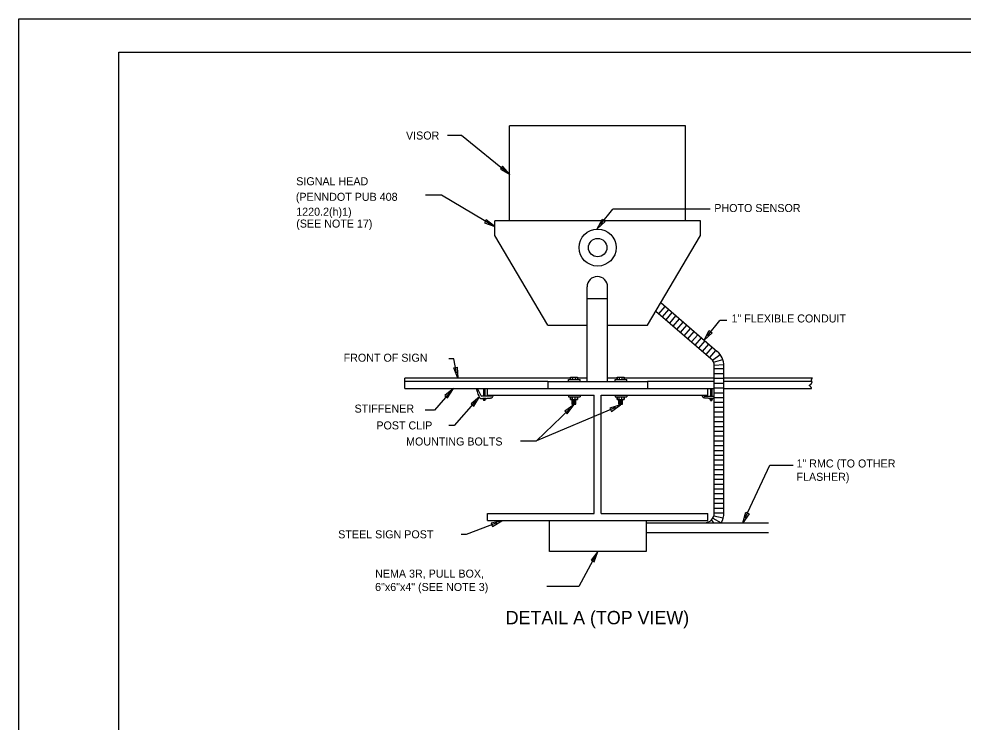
# Model space of a CAD drawing. Extents: x 1299104.6 to 1299141.5, y 239713.3 to 239735.3.
# Drawn here: x 1299104.62 to 1299118.77, y 239724.74 to 239735.27 of the extents above; entities that cross this region are included whole.
import ezdxf

# ---------------------------------------------------------------- set-up
doc = ezdxf.new("R2010")
doc.units = 0
for name, color, linetype in [('DIM TXT', 7, 'Continuous'), ('GS_plotshape_p', 7, 'Continuous'), ('Level 1', 7, 'Continuous'), ('PTEXT', 7, 'Continuous')]:
    doc.layers.add(name, color=color, linetype=linetype)

msp = doc.modelspace()

# ---------------------------------------------------------------- linework, layer by layer
at = {"layer": 'DIM TXT'}
for p, q in [((1299111.047, 239733.529), (1299111.254, 239733.529)), ((1299111.254, 239733.529), (1299111.982, 239732.944)), ((1299110.714, 239732.638), (1299110.957, 239732.638)), ((1299110.957, 239732.638), (1299111.755, 239732.162)), ((1299113.338, 239732.192), (1299113.522, 239732.422)), ((1299114.98, 239732.423), (1299113.522, 239732.422)), ((1299114.941, 239730.526), (1299115.125, 239730.756)), ((1299115.23, 239730.756), (1299115.125, 239730.756)), ((1299111.139, 239730.179), (1299111.065, 239730.179)), ((1299111.183, 239729.972), (1299111.139, 239730.179)), ((1299111.081, 239729.677), (1299110.849, 239729.413)), ((1299111.472, 239729.551), (1299111.148, 239729.182)), ((1299110.849, 239729.413), (1299110.712, 239729.413)), ((1299113.565, 239729.453), (1299112.38, 239728.951)), ((1299112.881, 239729.433), (1299112.38, 239728.951)), ((1299111.148, 239729.182), (1299111.065, 239729.182)), ((1299112.141, 239728.951), (1299112.38, 239728.951)), ((1299115.507, 239727.799), (1299115.877, 239728.587)), ((1299115.877, 239728.587), (1299116.225, 239728.587)), ((1299111.784, 239727.724), (1299111.326, 239727.549)), ((1299111.326, 239727.549), (1299111.252, 239727.549)), ((1299113.261, 239727.226), (1299113.014, 239726.77)), ((1299113.014, 239726.77), (1299112.534, 239726.77))]:
    msp.add_line(p, q, dxfattribs=at)
for points in [[(1299111.872, 239733.066), (1299111.838, 239733.024), (1299111.982, 239732.944)], [(1299111.627, 239732.264), (1299111.6, 239732.217), (1299111.755, 239732.162)], [(1299113.367, 239732.272), (1299113.409, 239732.239), (1299113.289, 239732.128)], [(1299114.969, 239730.606), (1299115.012, 239730.573), (1299114.891, 239730.462)], [(1299111.139, 239730.046), (1299111.192, 239730.057), (1299111.2, 239729.893)], [(1299111.007, 239729.634), (1299111.047, 239729.598), (1299111.135, 239729.737)], [(1299111.398, 239729.509), (1299111.438, 239729.473), (1299111.526, 239729.611)], [(1299112.804, 239729.397), (1299112.841, 239729.358), (1299112.939, 239729.49)], [(1299113.48, 239729.441), (1299113.505, 239729.393), (1299113.637, 239729.49)], [(1299115.517, 239727.884), (1299115.566, 239727.861), (1299115.473, 239727.726)], [(1299111.698, 239727.72), (1299111.718, 239727.67), (1299111.859, 239727.753)], [(1299113.199, 239727.167), (1299113.246, 239727.141), (1299113.3, 239727.297)]]:
    msp.add_lwpolyline(points, close=True, dxfattribs=at)
at = {"layer": 'GS_plotshape_p'}
msp.add_lwpolyline([(1299104.622, 239735.273), (1299138.622, 239735.273), (1299138.622, 239713.273), (1299104.622, 239713.273)], close=True, dxfattribs=at)
at = {"layer": 'Level 1'}
msp.add_lwpolyline([(1299138.122, 239713.773), (1299106.122, 239713.773), (1299106.122, 239734.773), (1299138.122, 239734.773)], close=True, dxfattribs=at)
at = {"layer": 'PTEXT'}
for p, q in [((1299114.614, 239733.673), (1299111.977, 239733.673)), ((1299111.977, 239732.249), (1299111.977, 239733.673)), ((1299114.614, 239732.249), (1299114.614, 239733.673)), ((1299114.836, 239732.249), (1299111.756, 239732.249)), ((1299111.756, 239732.027), (1299111.756, 239732.249)), ((1299114.836, 239732.027), (1299114.836, 239732.249)), ((1299112.551, 239730.686), (1299111.756, 239732.027)), ((1299114.041, 239730.686), (1299114.836, 239732.027)), ((1299113.138, 239729.84), (1299113.138, 239731.26)), ((1299113.446, 239729.84), (1299113.446, 239731.26)), ((1299113.138, 239731.086), (1299113.446, 239731.086)), ((1299114.212, 239730.857), (1299114.306, 239730.967)), ((1299114.241, 239731.023), (1299115.088, 239730.293)), ((1299114.166, 239730.897), (1299114.994, 239730.184)), ((1299114.267, 239730.81), (1299114.361, 239730.92)), ((1299114.321, 239730.763), (1299114.415, 239730.873)), ((1299114.376, 239730.716), (1299114.47, 239730.825)), ((1299112.551, 239730.686), (1299113.138, 239730.686)), ((1299113.446, 239730.686), (1299114.041, 239730.686)), ((1299114.43, 239730.669), (1299114.524, 239730.778)), ((1299114.485, 239730.622), (1299114.579, 239730.731)), ((1299114.539, 239730.575), (1299114.633, 239730.684)), ((1299114.594, 239730.528), (1299114.688, 239730.637)), ((1299114.648, 239730.481), (1299114.742, 239730.59)), ((1299114.703, 239730.434), (1299114.797, 239730.543)), ((1299114.757, 239730.387), (1299114.851, 239730.496)), ((1299114.812, 239730.34), (1299114.906, 239730.449)), ((1299114.866, 239730.293), (1299114.96, 239730.402)), ((1299114.921, 239730.246), (1299115.015, 239730.355)), ((1299114.975, 239730.199), (1299115.069, 239730.308)), ((1299115.016, 239730.159), (1299115.132, 239730.245)), ((1299115.033, 239730.129), (1299115.171, 239730.169)), ((1299115.043, 239730.088), (1299115.187, 239730.095)), ((1299115.044, 239727.87), (1299115.044, 239730.074)), ((1299115.044, 239730.034), (1299115.188, 239730.034)), ((1299115.044, 239729.962), (1299115.188, 239729.962)), ((1299115.188, 239727.87), (1299115.188, 239730.074)), ((1299110.407, 239729.737), (1299110.407, 239729.892)), ((1299112.889, 239729.892), (1299110.407, 239729.892)), ((1299112.551, 239729.84), (1299110.407, 239729.84)), ((1299112.551, 239729.84), (1299114.041, 239729.84)), ((1299112.551, 239729.84), (1299112.551, 239729.737)), ((1299112.859, 239729.87), (1299113.033, 239729.87)), ((1299112.859, 239729.845), (1299112.859, 239729.87)), ((1299112.889, 239729.906), (1299112.995, 239729.906)), ((1299112.889, 239729.906), (1299112.889, 239729.87)), ((1299112.889, 239729.88), (1299112.889, 239729.906)), ((1299112.919, 239729.906), (1299112.919, 239729.87)), ((1299112.96, 239729.906), (1299112.96, 239729.87)), ((1299112.995, 239729.87), (1299112.995, 239729.906)), ((1299112.995, 239729.906), (1299112.995, 239729.88)), ((1299113.138, 239729.892), (1299112.995, 239729.892)), ((1299113.033, 239729.845), (1299113.033, 239729.87)), ((1299113.588, 239729.892), (1299113.446, 239729.892)), ((1299113.559, 239729.87), (1299113.733, 239729.87)), ((1299113.559, 239729.845), (1299113.559, 239729.87)), ((1299113.588, 239729.906), (1299113.588, 239729.87)), ((1299113.588, 239729.88), (1299113.588, 239729.906)), ((1299113.588, 239729.906), (1299113.694, 239729.906)), ((1299113.618, 239729.906), (1299113.618, 239729.87)), ((1299113.659, 239729.906), (1299113.659, 239729.87)), ((1299113.694, 239729.87), (1299113.694, 239729.906)), ((1299113.694, 239729.906), (1299113.694, 239729.88)), ((1299115.044, 239729.892), (1299113.694, 239729.892)), ((1299113.733, 239729.845), (1299113.733, 239729.87)), ((1299114.041, 239729.84), (1299114.041, 239729.737)), ((1299115.044, 239729.84), (1299114.041, 239729.84)), ((1299115.044, 239729.89), (1299115.188, 239729.89)), ((1299115.044, 239729.818), (1299115.188, 239729.818)), ((1299116.514, 239729.892), (1299115.188, 239729.892)), ((1299116.507, 239729.84), (1299115.188, 239729.84)), ((1299110.407, 239729.737), (1299115.044, 239729.737)), ((1299111.55, 239729.626), (1299111.493, 239729.737)), ((1299111.586, 239729.737), (1299111.586, 239729.62)), ((1299111.603, 239729.734), (1299111.589, 239729.734)), ((1299111.603, 239729.729), (1299111.589, 239729.729)), ((1299111.603, 239729.723), (1299111.589, 239729.723)), ((1299111.603, 239729.718), (1299111.589, 239729.718)), ((1299111.603, 239729.713), (1299111.589, 239729.713)), ((1299111.603, 239729.707), (1299111.589, 239729.707)), ((1299111.603, 239729.702), (1299111.589, 239729.702)), ((1299111.603, 239729.696), (1299111.589, 239729.696)), ((1299111.603, 239729.691), (1299111.589, 239729.691)), ((1299111.603, 239729.686), (1299111.589, 239729.686)), ((1299111.603, 239729.68), (1299111.589, 239729.68)), ((1299111.603, 239729.675), (1299111.589, 239729.675)), ((1299111.606, 239729.737), (1299111.606, 239729.62)), ((1299111.645, 239729.635), (1299111.645, 239729.737)), ((1299114.947, 239729.635), (1299114.947, 239729.737)), ((1299114.986, 239729.737), (1299114.986, 239729.62)), ((1299114.989, 239729.734), (1299115.003, 239729.734)), ((1299114.989, 239729.729), (1299115.003, 239729.729)), ((1299114.989, 239729.723), (1299115.003, 239729.723)), ((1299114.989, 239729.718), (1299115.003, 239729.718)), ((1299114.989, 239729.713), (1299115.003, 239729.713)), ((1299114.989, 239729.707), (1299115.003, 239729.707)), ((1299114.989, 239729.702), (1299115.003, 239729.702)), ((1299114.989, 239729.696), (1299115.003, 239729.696)), ((1299114.989, 239729.691), (1299115.003, 239729.691)), ((1299114.989, 239729.686), (1299115.003, 239729.686)), ((1299114.989, 239729.68), (1299115.003, 239729.68)), ((1299114.989, 239729.675), (1299115.003, 239729.675)), ((1299115.006, 239729.737), (1299115.006, 239729.62)), ((1299115.044, 239729.746), (1299115.188, 239729.746)), ((1299115.044, 239729.674), (1299115.188, 239729.674)), ((1299115.188, 239729.737), (1299116.503, 239729.737)), ((1299111.696, 239729.62), (1299111.56, 239729.62)), ((1299111.619, 239729.588), (1299111.573, 239729.588)), ((1299111.573, 239729.588), (1299111.573, 239729.583)), ((1299111.619, 239729.583), (1299111.573, 239729.583)), ((1299111.578, 239729.583), (1299111.578, 239729.573)), ((1299111.614, 239729.573), (1299111.578, 239729.573)), ((1299111.584, 239729.583), (1299111.584, 239729.573)), ((1299111.586, 239729.573), (1299111.586, 239729.559)), ((1299111.606, 239729.559), (1299111.586, 239729.559)), ((1299111.603, 239729.669), (1299111.589, 239729.669)), ((1299111.603, 239729.664), (1299111.589, 239729.664)), ((1299111.603, 239729.659), (1299111.589, 239729.659)), ((1299111.603, 239729.653), (1299111.589, 239729.653)), ((1299111.603, 239729.648), (1299111.589, 239729.648)), ((1299111.603, 239729.642), (1299111.589, 239729.642)), ((1299111.603, 239729.637), (1299111.589, 239729.637)), ((1299111.603, 239729.632), (1299111.589, 239729.632)), ((1299111.603, 239729.626), (1299111.589, 239729.626)), ((1299111.603, 239729.571), (1299111.589, 239729.571)), ((1299111.603, 239729.566), (1299111.589, 239729.566)), ((1299111.603, 239729.56), (1299111.589, 239729.56)), ((1299111.596, 239729.583), (1299111.596, 239729.573)), ((1299111.606, 239729.573), (1299111.606, 239729.559)), ((1299111.608, 239729.583), (1299111.608, 239729.573)), ((1299111.614, 239729.583), (1299111.614, 239729.573)), ((1299111.619, 239729.588), (1299111.619, 239729.583)), ((1299111.645, 239729.635), (1299113.245, 239729.635)), ((1299111.711, 239729.635), (1299111.706, 239729.626)), ((1299112.859, 239729.635), (1299112.859, 239729.611)), ((1299112.859, 239729.611), (1299113.033, 239729.611)), ((1299112.889, 239729.574), (1299112.889, 239729.611)), ((1299112.889, 239729.6), (1299112.889, 239729.574)), ((1299112.889, 239729.574), (1299112.995, 239729.574)), ((1299112.91, 239729.574), (1299112.91, 239729.501)), ((1299112.91, 239729.556), (1299112.969, 239729.556)), ((1299112.91, 239729.538), (1299112.969, 239729.538)), ((1299112.919, 239729.574), (1299112.919, 239729.611)), ((1299112.96, 239729.574), (1299112.96, 239729.611)), ((1299112.969, 239729.501), (1299112.969, 239729.574)), ((1299112.995, 239729.611), (1299112.995, 239729.574)), ((1299112.995, 239729.574), (1299112.995, 239729.6)), ((1299113.033, 239729.635), (1299113.033, 239729.611)), ((1299113.245, 239727.863), (1299113.245, 239729.635)), ((1299113.347, 239727.863), (1299113.347, 239729.635)), ((1299113.347, 239729.635), (1299114.947, 239729.635)), ((1299113.559, 239729.635), (1299113.559, 239729.611)), ((1299113.559, 239729.611), (1299113.733, 239729.611)), ((1299113.588, 239729.574), (1299113.588, 239729.611)), ((1299113.588, 239729.6), (1299113.588, 239729.574)), ((1299113.588, 239729.574), (1299113.694, 239729.574)), ((1299113.609, 239729.574), (1299113.609, 239729.501)), ((1299113.609, 239729.556), (1299113.669, 239729.556)), ((1299113.609, 239729.538), (1299113.669, 239729.538)), ((1299113.618, 239729.574), (1299113.618, 239729.611)), ((1299113.659, 239729.574), (1299113.659, 239729.611)), ((1299113.669, 239729.501), (1299113.669, 239729.574)), ((1299113.694, 239729.611), (1299113.694, 239729.574)), ((1299113.694, 239729.574), (1299113.694, 239729.6)), ((1299113.733, 239729.635), (1299113.733, 239729.611)), ((1299114.881, 239729.635), (1299114.886, 239729.626)), ((1299114.895, 239729.62), (1299115.032, 239729.62)), ((1299114.973, 239729.588), (1299114.973, 239729.583)), ((1299114.973, 239729.588), (1299115.019, 239729.588)), ((1299114.973, 239729.583), (1299115.019, 239729.583)), ((1299114.978, 239729.583), (1299114.978, 239729.573)), ((1299114.978, 239729.573), (1299115.014, 239729.573)), ((1299114.984, 239729.583), (1299114.984, 239729.573)), ((1299114.986, 239729.573), (1299114.986, 239729.559)), ((1299114.986, 239729.559), (1299115.006, 239729.559)), ((1299114.989, 239729.669), (1299115.003, 239729.669)), ((1299114.989, 239729.664), (1299115.003, 239729.664)), ((1299114.989, 239729.659), (1299115.003, 239729.659)), ((1299114.989, 239729.653), (1299115.003, 239729.653)), ((1299114.989, 239729.648), (1299115.003, 239729.648)), ((1299114.989, 239729.642), (1299115.003, 239729.642)), ((1299114.989, 239729.637), (1299115.003, 239729.637)), ((1299114.989, 239729.632), (1299115.003, 239729.632)), ((1299114.989, 239729.626), (1299115.003, 239729.626)), ((1299114.989, 239729.571), (1299115.003, 239729.571)), ((1299114.989, 239729.566), (1299115.003, 239729.566)), ((1299114.989, 239729.56), (1299115.003, 239729.56)), ((1299114.996, 239729.583), (1299114.996, 239729.573)), ((1299115.006, 239729.573), (1299115.006, 239729.559)), ((1299115.008, 239729.583), (1299115.008, 239729.573)), ((1299115.014, 239729.583), (1299115.014, 239729.573)), ((1299115.019, 239729.588), (1299115.019, 239729.583)), ((1299115.042, 239729.626), (1299115.044, 239729.629)), ((1299115.044, 239729.602), (1299115.188, 239729.602)), ((1299112.91, 239729.519), (1299112.969, 239729.519)), ((1299112.91, 239729.501), (1299112.969, 239729.501)), ((1299113.609, 239729.519), (1299113.669, 239729.519)), ((1299113.609, 239729.501), (1299113.669, 239729.501)), ((1299115.044, 239729.53), (1299115.188, 239729.53)), ((1299115.044, 239729.458), (1299115.188, 239729.458)), ((1299115.044, 239729.386), (1299115.188, 239729.386)), ((1299115.044, 239729.314), (1299115.188, 239729.314)), ((1299115.044, 239729.242), (1299115.188, 239729.242)), ((1299115.044, 239729.17), (1299115.188, 239729.17)), ((1299115.044, 239729.098), (1299115.188, 239729.098)), ((1299115.044, 239729.026), (1299115.188, 239729.026)), ((1299115.044, 239728.954), (1299115.188, 239728.954)), ((1299115.044, 239728.882), (1299115.188, 239728.882)), ((1299115.044, 239728.81), (1299115.188, 239728.81)), ((1299115.044, 239728.738), (1299115.188, 239728.738)), ((1299115.044, 239728.666), (1299115.188, 239728.666)), ((1299115.044, 239728.594), (1299115.188, 239728.594)), ((1299115.044, 239728.522), (1299115.188, 239728.522)), ((1299115.044, 239728.45), (1299115.188, 239728.45)), ((1299115.044, 239728.378), (1299115.188, 239728.378)), ((1299115.044, 239728.306), (1299115.188, 239728.306)), ((1299115.044, 239728.234), (1299115.188, 239728.234)), ((1299115.044, 239728.162), (1299115.188, 239728.162)), ((1299115.044, 239728.162), (1299115.188, 239728.162)), ((1299115.044, 239728.09), (1299115.188, 239728.09)), ((1299115.044, 239728.018), (1299115.188, 239728.018)), ((1299111.645, 239727.863), (1299113.245, 239727.863)), ((1299111.645, 239727.761), (1299111.645, 239727.863)), ((1299113.347, 239727.863), (1299114.947, 239727.863)), ((1299114.947, 239727.761), (1299114.947, 239727.863)), ((1299115.044, 239727.946), (1299115.188, 239727.946)), ((1299115.044, 239727.874), (1299115.188, 239727.874)), ((1299111.645, 239727.761), (1299114.947, 239727.761)), ((1299112.576, 239727.297), (1299112.576, 239727.761)), ((1299114.024, 239727.761), (1299114.024, 239727.297)), ((1299114.024, 239727.726), (1299115.855, 239727.726)), ((1299115.001, 239727.767), (1299115.031, 239727.726)), ((1299115.023, 239727.796), (1299115.147, 239727.726)), ((1299115.038, 239727.831), (1299115.179, 239727.802)), ((1299114.024, 239727.582), (1299115.855, 239727.582)), ((1299114.024, 239727.297), (1299112.576, 239727.297))]:
    msp.add_line(p, q, dxfattribs=at)
for points in [[(1299111.473, 239729.737), (1299111.488, 239729.693), (1299111.502, 239729.654), (1299111.513, 239729.627), (1299111.521, 239729.608), (1299111.528, 239729.597), (1299111.534, 239729.591), (1299111.54, 239729.589), (1299111.547, 239729.589), (1299111.555, 239729.589), (1299111.565, 239729.589), (1299111.575, 239729.589), (1299111.586, 239729.589), (1299111.598, 239729.589), (1299111.609, 239729.589), (1299111.621, 239729.589), (1299111.632, 239729.589), (1299111.642, 239729.59), (1299111.652, 239729.59), (1299111.661, 239729.591), (1299111.67, 239729.591), (1299111.677, 239729.592), (1299111.685, 239729.593), (1299111.691, 239729.594), (1299111.697, 239729.595), (1299111.703, 239729.596), (1299111.708, 239729.598), (1299111.713, 239729.6), (1299111.717, 239729.604), (1299111.722, 239729.609), (1299111.726, 239729.616), (1299111.731, 239729.625), (1299111.735, 239729.635)], [(1299115.044, 239729.589), (1299115.037, 239729.589), (1299115.027, 239729.589), (1299115.017, 239729.589), (1299115.006, 239729.589), (1299114.994, 239729.589), (1299114.982, 239729.589), (1299114.971, 239729.589), (1299114.96, 239729.589), (1299114.95, 239729.59), (1299114.94, 239729.59), (1299114.931, 239729.591), (1299114.922, 239729.591), (1299114.915, 239729.592), (1299114.907, 239729.593), (1299114.901, 239729.594), (1299114.895, 239729.595), (1299114.889, 239729.596), (1299114.884, 239729.598), (1299114.879, 239729.6), (1299114.875, 239729.604), (1299114.87, 239729.609), (1299114.866, 239729.616), (1299114.861, 239729.625), (1299114.857, 239729.635)]]:
    msp.add_lwpolyline(points, dxfattribs=at)
for radius in [0.277, 0.138]:
    msp.add_circle((1299113.296, 239731.847), radius, dxfattribs=at)
for centre, radius, start, end in [((1299113.292, 239731.26), 0.154, 0, 180), ((1299114.9, 239730.074), 0.288, 0, 49.2333), ((1299114.9, 239730.074), 0.144, 0, 49.2333), ((1299111.56, 239729.63), 0.0108, 206.9824, 270), ((1299111.696, 239729.63), 0.0108, 270, 332.8619), ((1299114.895, 239729.63), 0.0108, 207.1381, 270), ((1299115.032, 239729.63), 0.0108, 270, 333.0176), ((1299114.9, 239727.87), 0.144, 270, 0), ((1299114.9, 239727.87), 0.288, 330, 0)]:
    msp.add_arc(centre, radius, start, end, dxfattribs=at)
msp.add_open_spline([(1299116.503, 239729.737), (1299116.493, 239729.764), (1299116.462, 239729.784), (1299116.493, 239729.799), (1299116.512, 239729.831), (1299116.503, 239729.847), (1299116.501, 239729.872), (1299116.514, 239729.892)], degree=2, dxfattribs=at)

# ---------------------------------------------------------------- texts
at = {"layer": 'DIM TXT'}
for s, height, p in [('VISOR', 0.12, (1299110.424, 239733.466)), ('SIGNAL HEAD ', 0.12, (1299108.779, 239732.781)), ('(PENNDOT PUB 408 ', 0.12, (1299108.773, 239732.548)), ('1220.2(h)1)', 0.12, (1299108.779, 239732.325)), ('PHOTO SENSOR', 0.12, (1299115.044, 239732.38)), ('(SEE NOTE 17)', 0.12, (1299108.779, 239732.147)), ('1" FLEXIBLE CONDUIT', 0.12, (1299115.302, 239730.726)), ('FRONT OF SIGN', 0.12, (1299109.489, 239730.138)), ('STIFFENER', 0.12, (1299109.653, 239729.376)), ('POST CLIP', 0.12, (1299109.98, 239729.124)), ('MOUNTING BOLTS', 0.12, (1299110.425, 239728.883)), ('1" RMC (TO OTHER ', 0.12, (1299116.276, 239728.554)), ('FLASHER)', 0.12, (1299116.276, 239728.354)), ('STEEL SIGN POST', 0.12, (1299109.408, 239727.493)), ('NEMA 3R, PULL BOX, ', 0.12, (1299109.961, 239726.904)), ('6"x6"x4" (SEE NOTE 3)', 0.12, (1299109.961, 239726.704)), ('DETAIL A (TOP VIEW)', 0.2, (1299111.918, 239726.205))]:
    msp.add_text(s, height=height, dxfattribs=at).set_placement(p)

doc.saveas('drawing.dxf')
